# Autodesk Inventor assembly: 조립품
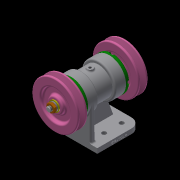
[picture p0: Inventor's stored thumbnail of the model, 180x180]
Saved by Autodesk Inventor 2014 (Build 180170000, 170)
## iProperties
Created: 2020-06
Part Number: 조립품
Document SubType Name: Assembly
Designer: kh
Author: kh
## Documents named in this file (12)
- C:\Users\kh\Desktop\700606V1049\조립품.iam
- C:\Users\kh\Desktop\700606V1049\본체.ipt
- C:\Users\kh\Desktop\700606V1049\베어링 6204.ipt
- C:\Users\kh\Desktop\700606V1049\축.ipt
- C:\Users\kh\Desktop\700606V1049\커버.ipt
- C:\Users\kh\Desktop\700606V1049\오일 실 20 32 5.ipt
- C:\Users\kh\Desktop\700606V1049\키 5x5x12.ipt
- C:\Users\kh\Desktop\700606V1049\V-벨트풀리.ipt
- C:\Users\kh\Desktop\700606V1049\평면 와셔 10x21.ipt
- C:\Users\kh\Desktop\700606V1049\스프링 와셔 10.ipt
- C:\Users\kh\Desktop\700606V1049\너트 M10.ipt
- C:\Users\kh\Desktop\700606V1049\볼트 M4.ipt
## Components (2 placed, 1 different names)
1. V-벨트풀리:1 — Mate:23, Mate:24, Mate:25, Mate:30
2. V-벨트풀리:2 — Mate:26, Mate:27, Mate:28, Mate:32
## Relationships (8: Mate 8)
- Mate:23: V-벨트풀리:1
- Mate:24: V-벨트풀리:1
- Mate:25: V-벨트풀리:1
- Mate:26: V-벨트풀리:2
- Mate:27: V-벨트풀리:2
- Mate:28: V-벨트풀리:2
- Mate:30: V-벨트풀리:1
- Mate:32: V-벨트풀리:2
